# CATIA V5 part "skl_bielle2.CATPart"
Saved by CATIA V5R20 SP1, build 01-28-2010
Part number: skl_bielle2
Publications: "Droite.1", "Droite.2", "Droite.3", "Droite.4", "Plan xy"
Bounding box of the stored display mesh (mm): x 345.35 to 638.046, y 818.683 to 1028.275, z 0 to 100
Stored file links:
  C:\Users\Manon\Desktop\IAO\SKL_rlanglais\skl_bielle2.CATPart
  C:\Users\Manon\Desktop\IAO\SKL_rlanglais\SKL_rlanglais.CATProduct
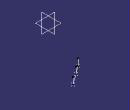
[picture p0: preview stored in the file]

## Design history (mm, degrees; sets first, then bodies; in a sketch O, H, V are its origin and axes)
Set1
  Point1 "E": linked copy from another document
  Point2 "C": linked copy from another document
  Point3 "B": linked copy from another document
Set2
  Line1: type PtPt, LineSecondUpto Point2, FirstPoint Point1, SecondPoint Point3
  Line2: type Normal, RefPoint Point3, RefSkin xy-plane, Start 0, End 100
  Line3: type Normal, RefPoint Point2, RefSkin xy-plane, Start 0, End 100
  Line4: type Normal, RefPoint Point1, RefSkin xy-plane, Start 0, End 100
Body1 (main body)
